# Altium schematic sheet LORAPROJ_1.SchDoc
size A; SheetNumber: 1; SheetTotal: 3
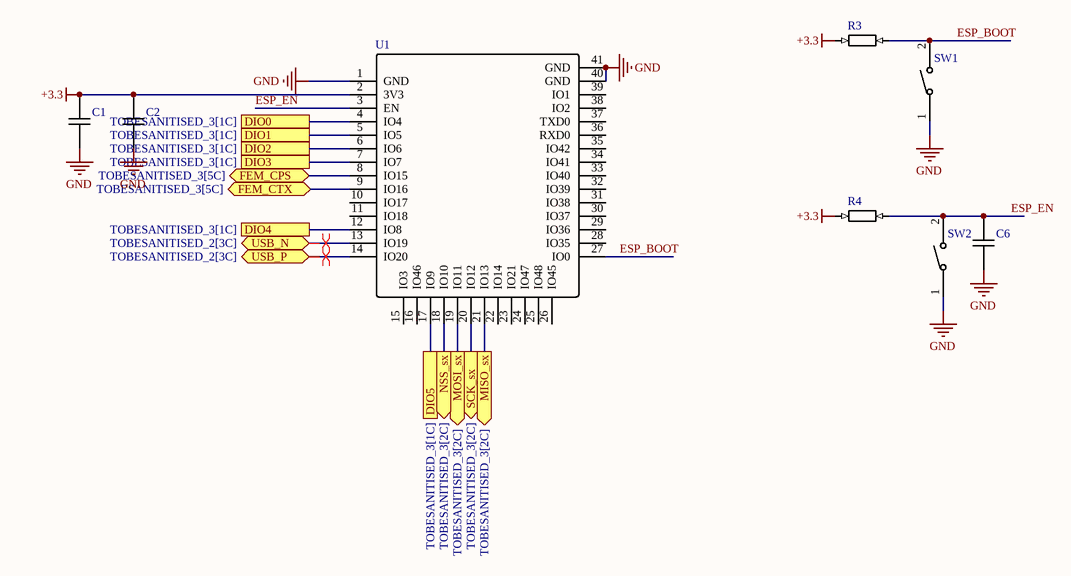
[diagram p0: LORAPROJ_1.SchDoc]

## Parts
C1  (no value)  [CAP_0603]
C2  (no value)  [CAP_0603]
C6  (no value)  [CAP_0603]
R3  (no value)  [RES_0603]
R4  (no value)  [RES_0603]
SW1  (no value)  [SW_SMD_3.9x3.0]
SW2  (no value)  [SW_SMD_3.9x3.0]
U1  (no value)  [RF_MODULE_SMD]

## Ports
DIO0 (see TOBESANITISED_3[1C]), DIO1 (see TOBESANITISED_3[1C]), DIO2 (see TOBESANITISED_3[1C]), DIO3 (see TOBESANITISED_3[1C]), DIO4 (see TOBESANITISED_3[1C]), DIO5 (see TOBESANITISED_3[1C]), FEM_CPS (bidir, see TOBESANITISED_3[5C]), FEM_CTX (bidir, see TOBESANITISED_3[5C]), MISO_sx (out, see TOBESANITISED_3[2C]), MOSI_sx (out, see TOBESANITISED_3[2C]), NSS_sx (out, see TOBESANITISED_3[2C]), SCK_sx (out, see TOBESANITISED_3[2C]), USB_N (bidir, see TOBESANITISED_2[3C]), USB_P (bidir, see TOBESANITISED_2[3C])

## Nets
+3.3: C1.2 C2.2 R3.1 R4.1 U1.2(3V3)
GND: C1.1 C2.1 C6.1 SW1.1 SW2.1 U1.1(GND) U1.40(GND) U1.41(GND)
DIO0: U1.4(IO4) ; port DIO0
DIO1: U1.5(IO5) ; port DIO1
DIO2: U1.6(IO6) ; port DIO2
DIO3: U1.7(IO7) ; port DIO3
DIO4: U1.12(IO8) ; port DIO4
DIO5: U1.17(IO9) ; port DIO5
ESP_BOOT: R3.2 SW1.2 U1.27(IO0)
ESP_EN: C6.2 R4.2 SW2.2 U1.3(EN)
FEM_CPS: U1.8(IO15) ; port FEM_CPS
FEM_CTX: U1.9(IO16) ; port FEM_CTX
MISO_sx: U1.21(IO13) ; port MISO_sx
MOSI_sx: U1.19(IO11) ; port MOSI_sx
NSS_sx: U1.18(IO10) ; port NSS_sx
SCK_sx: U1.20(IO12) ; port SCK_sx
USB_N: U1.13(IO19) ; port USB_N
USB_P: U1.14(IO20) ; port USB_P

Not connected (* = marked no-connect by the designer): U1 10(IO17) 11(IO18) 15(IO3) 16(IO46) 22(IO14) 23(IO21) 24(IO47) 25(IO48) 26(IO45) 28(IO35) 29(IO36) 30(IO37) 31(IO38) 32(IO39) 33(IO40) 34(IO41) 35(IO42) 36(RXD0) 37(TXD0) 38(IO2) 39(IO1)

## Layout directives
differential pair: USB_N, USB_P

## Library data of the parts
C1 C2 C6 = CAP
R3 R4 = RES
SW1 SW2 = SW
U1 = IC_U1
